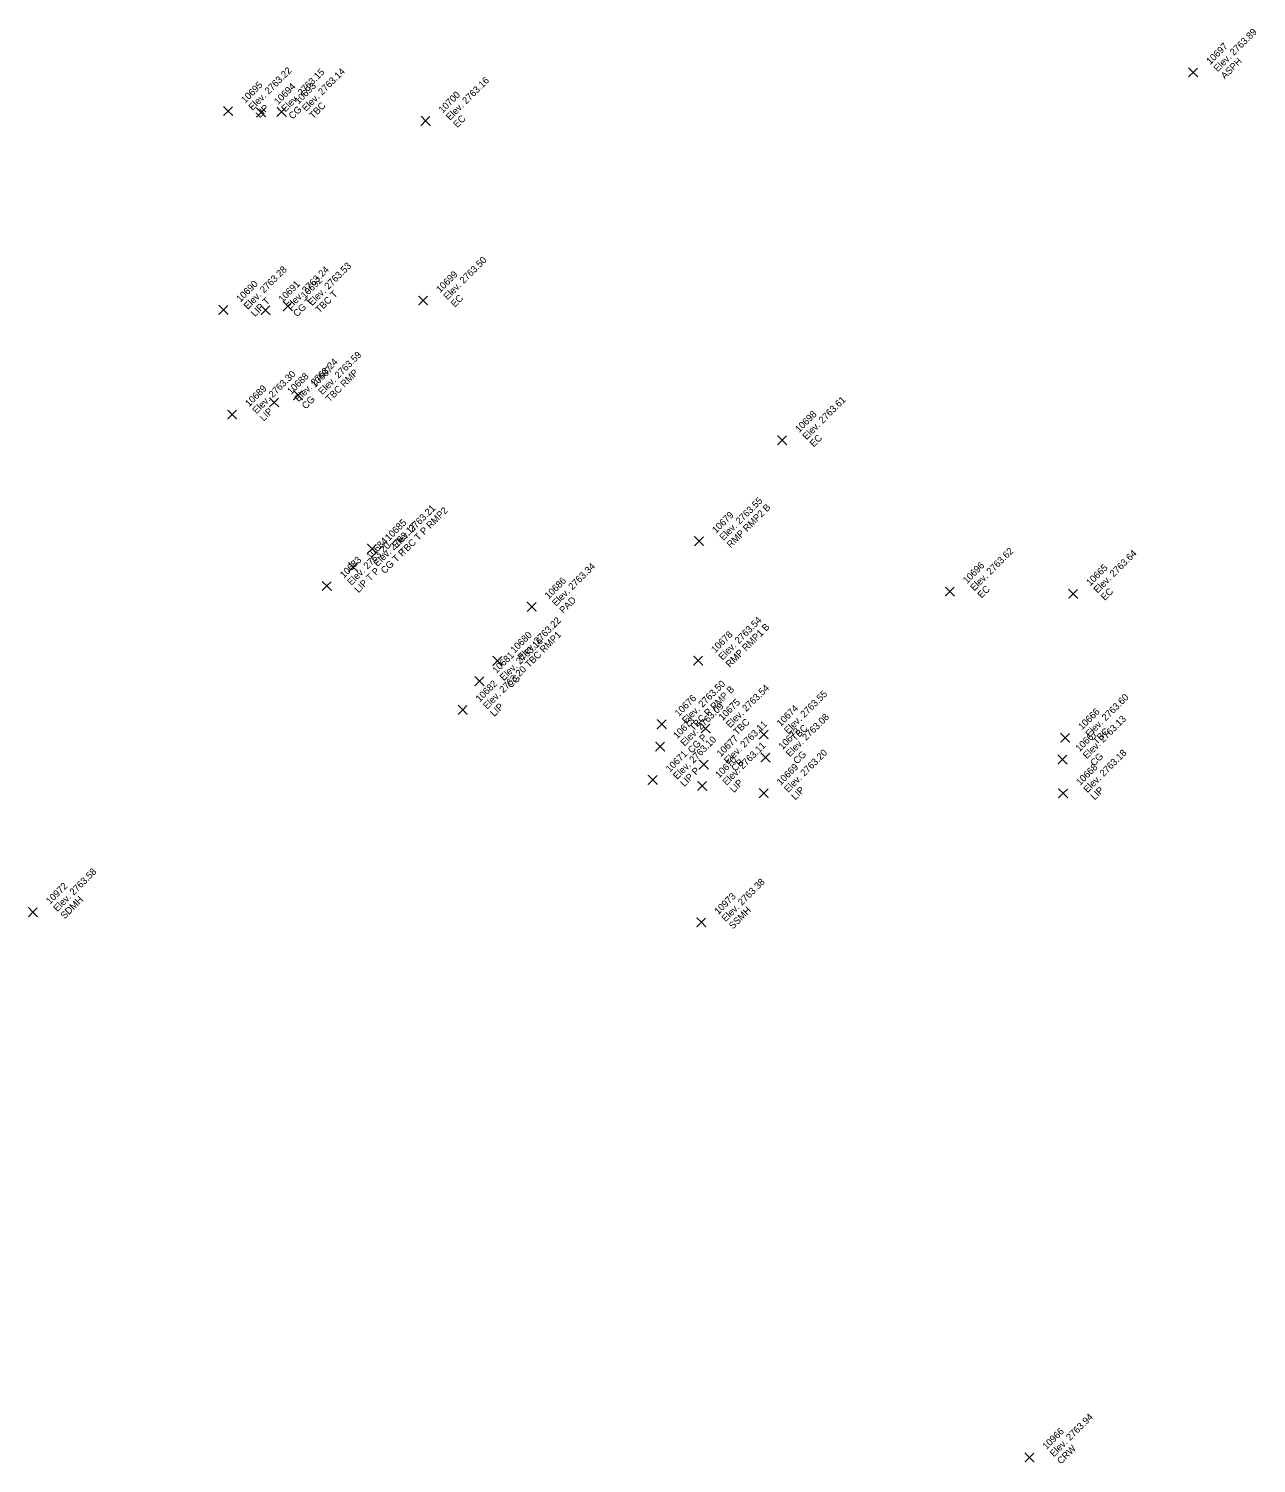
# Model space of a CAD drawing. Extents: x 2493999 to 2503109, y 700767 to 706646.
# Drawn here: x 2502612.8 to 2502655.7, y 701336 to 701386.1 of the extents above; entities that cross this region are included whole.
import ezdxf

# ---------------------------------------------------------------- set-up
doc = ezdxf.new("R2010")
doc.units = 0
doc.layers.add('ALG_CL_BLUE_Horiz', color=7, linetype='Continuous')
doc.layers.add('DES_SURFACE_Existing-Ground', color=7, linetype='Continuous')

msp = doc.modelspace()

# ---------------------------------------------------------------- linework, layer by layer
at = {"layer": 'ALG_CL_BLUE_Horiz'}
for points in [[(2502653.473, 701384.558), (2502653.323, 701384.708), (2502653.473, 701384.558), (2502653.323, 701384.408), (2502653.473, 701384.558), (2502653.623, 701384.408), (2502653.473, 701384.558), (2502653.623, 701384.708)], [(2502619.797, 701383.208), (2502619.647, 701383.358), (2502619.797, 701383.208), (2502619.647, 701383.058), (2502619.797, 701383.208), (2502619.947, 701383.058), (2502619.797, 701383.208), (2502619.947, 701383.358)], [(2502620.945, 701383.156), (2502620.795, 701383.306), (2502620.945, 701383.156), (2502620.795, 701383.006), (2502620.945, 701383.156), (2502621.095, 701383.006), (2502620.945, 701383.156), (2502621.095, 701383.306)], [(2502621.661, 701383.177), (2502621.511, 701383.327), (2502621.661, 701383.177), (2502621.511, 701383.027), (2502621.661, 701383.177), (2502621.811, 701383.027), (2502621.661, 701383.177), (2502621.811, 701383.327)], [(2502626.688, 701382.864), (2502626.538, 701383.014), (2502626.688, 701382.864), (2502626.538, 701382.714), (2502626.688, 701382.864), (2502626.838, 701382.714), (2502626.688, 701382.864), (2502626.838, 701383.014)], [(2502626.601, 701376.599), (2502626.451, 701376.749), (2502626.601, 701376.599), (2502626.451, 701376.449), (2502626.601, 701376.599), (2502626.751, 701376.449), (2502626.601, 701376.599), (2502626.751, 701376.749)], [(2502619.631, 701376.268), (2502619.481, 701376.418), (2502619.631, 701376.268), (2502619.481, 701376.118), (2502619.631, 701376.268), (2502619.781, 701376.118), (2502619.631, 701376.268), (2502619.781, 701376.418)], [(2502621.102, 701376.262), (2502620.952, 701376.412), (2502621.102, 701376.262), (2502620.952, 701376.112), (2502621.102, 701376.262), (2502621.252, 701376.112), (2502621.102, 701376.262), (2502621.252, 701376.412)], [(2502621.878, 701376.397), (2502621.728, 701376.547), (2502621.878, 701376.397), (2502621.728, 701376.247), (2502621.878, 701376.397), (2502622.028, 701376.247), (2502621.878, 701376.397), (2502622.028, 701376.547)], [(2502622.235, 701373.291), (2502622.085, 701373.441), (2502622.235, 701373.291), (2502622.085, 701373.141), (2502622.235, 701373.291), (2502622.385, 701373.141), (2502622.235, 701373.291), (2502622.385, 701373.441)], [(2502619.937, 701372.621), (2502619.787, 701372.771), (2502619.937, 701372.621), (2502619.787, 701372.471), (2502619.937, 701372.621), (2502620.087, 701372.471), (2502619.937, 701372.621), (2502620.087, 701372.771)], [(2502621.405, 701373.045), (2502621.255, 701373.195), (2502621.405, 701373.045), (2502621.255, 701372.895), (2502621.405, 701373.045), (2502621.555, 701372.895), (2502621.405, 701373.045), (2502621.555, 701373.195)], [(2502639.128, 701371.723), (2502638.978, 701371.873), (2502639.128, 701371.723), (2502638.978, 701371.573), (2502639.128, 701371.723), (2502639.278, 701371.573), (2502639.128, 701371.723), (2502639.278, 701371.873)], [(2502636.23, 701368.203), (2502636.08, 701368.353), (2502636.23, 701368.203), (2502636.08, 701368.053), (2502636.23, 701368.203), (2502636.38, 701368.053), (2502636.23, 701368.203), (2502636.38, 701368.353)], [(2502624.817, 701367.94), (2502624.667, 701368.09), (2502624.817, 701367.94), (2502624.667, 701367.79), (2502624.817, 701367.94), (2502624.967, 701367.79), (2502624.817, 701367.94), (2502624.967, 701368.09)], [(2502624.16, 701367.3), (2502624.01, 701367.45), (2502624.16, 701367.3), (2502624.01, 701367.15), (2502624.16, 701367.3), (2502624.31, 701367.15), (2502624.16, 701367.3), (2502624.31, 701367.45)], [(2502623.244, 701366.638), (2502623.094, 701366.788), (2502623.244, 701366.638), (2502623.094, 701366.488), (2502623.244, 701366.638), (2502623.394, 701366.488), (2502623.244, 701366.638), (2502623.394, 701366.788)], [(2502644.981, 701366.446), (2502644.831, 701366.596), (2502644.981, 701366.446), (2502644.831, 701366.296), (2502644.981, 701366.446), (2502645.131, 701366.296), (2502644.981, 701366.446), (2502645.131, 701366.596)], [(2502649.283, 701366.366), (2502649.133, 701366.516), (2502649.283, 701366.366), (2502649.133, 701366.216), (2502649.283, 701366.366), (2502649.433, 701366.216), (2502649.283, 701366.366), (2502649.433, 701366.516)], [(2502630.39, 701365.914), (2502630.24, 701366.064), (2502630.39, 701365.914), (2502630.24, 701365.764), (2502630.39, 701365.914), (2502630.54, 701365.764), (2502630.39, 701365.914), (2502630.54, 701366.064)], [(2502629.193, 701364.023), (2502629.043, 701364.173), (2502629.193, 701364.023), (2502629.043, 701363.873), (2502629.193, 701364.023), (2502629.343, 701363.873), (2502629.193, 701364.023), (2502629.343, 701364.173)], [(2502636.197, 701364.035), (2502636.047, 701364.185), (2502636.197, 701364.035), (2502636.047, 701363.885), (2502636.197, 701364.035), (2502636.347, 701363.885), (2502636.197, 701364.035), (2502636.347, 701364.185)], [(2502628.565, 701363.314), (2502628.415, 701363.464), (2502628.565, 701363.314), (2502628.415, 701363.164), (2502628.565, 701363.314), (2502628.715, 701363.164), (2502628.565, 701363.314), (2502628.715, 701363.464)], [(2502627.981, 701362.321), (2502627.831, 701362.471), (2502627.981, 701362.321), (2502627.831, 701362.171), (2502627.981, 701362.321), (2502628.131, 701362.171), (2502627.981, 701362.321), (2502628.131, 701362.471)], [(2502634.928, 701361.815), (2502634.778, 701361.965), (2502634.928, 701361.815), (2502634.778, 701361.665), (2502634.928, 701361.815), (2502635.078, 701361.665), (2502634.928, 701361.815), (2502635.078, 701361.965)], [(2502636.458, 701361.671), (2502636.308, 701361.821), (2502636.458, 701361.671), (2502636.308, 701361.521), (2502636.458, 701361.671), (2502636.608, 701361.521), (2502636.458, 701361.671), (2502636.608, 701361.821)], [(2502638.485, 701361.461), (2502638.335, 701361.611), (2502638.485, 701361.461), (2502638.335, 701361.311), (2502638.485, 701361.461), (2502638.635, 701361.311), (2502638.485, 701361.461), (2502638.635, 701361.611)], [(2502649.003, 701361.345), (2502648.853, 701361.495), (2502649.003, 701361.345), (2502648.853, 701361.195), (2502649.003, 701361.345), (2502649.153, 701361.195), (2502649.003, 701361.345), (2502649.153, 701361.495)], [(2502634.872, 701361.035), (2502634.722, 701361.185), (2502634.872, 701361.035), (2502634.722, 701360.885), (2502634.872, 701361.035), (2502635.022, 701360.885), (2502634.872, 701361.035), (2502635.022, 701361.185)], [(2502638.55, 701360.659), (2502638.4, 701360.809), (2502638.55, 701360.659), (2502638.4, 701360.509), (2502638.55, 701360.659), (2502638.7, 701360.509), (2502638.55, 701360.659), (2502638.7, 701360.809)], [(2502648.912, 701360.589), (2502648.762, 701360.739), (2502648.912, 701360.589), (2502648.762, 701360.439), (2502648.912, 701360.589), (2502649.062, 701360.439), (2502648.912, 701360.589), (2502649.062, 701360.739)], [(2502636.392, 701360.408), (2502636.242, 701360.558), (2502636.392, 701360.408), (2502636.242, 701360.258), (2502636.392, 701360.408), (2502636.542, 701360.258), (2502636.392, 701360.408), (2502636.542, 701360.558)], [(2502634.613, 701359.871), (2502634.463, 701360.021), (2502634.613, 701359.871), (2502634.463, 701359.721), (2502634.613, 701359.871), (2502634.763, 701359.721), (2502634.613, 701359.871), (2502634.763, 701360.021)], [(2502636.338, 701359.664), (2502636.188, 701359.814), (2502636.338, 701359.664), (2502636.188, 701359.514), (2502636.338, 701359.664), (2502636.488, 701359.514), (2502636.338, 701359.664), (2502636.488, 701359.814)], [(2502638.486, 701359.411), (2502638.336, 701359.561), (2502638.486, 701359.411), (2502638.336, 701359.261), (2502638.486, 701359.411), (2502638.636, 701359.261), (2502638.486, 701359.411), (2502638.636, 701359.561)], [(2502648.93, 701359.405), (2502648.78, 701359.555), (2502648.93, 701359.405), (2502648.78, 701359.255), (2502648.93, 701359.405), (2502649.08, 701359.255), (2502648.93, 701359.405), (2502649.08, 701359.555)], [(2502612.988, 701355.261), (2502612.838, 701355.411), (2502612.988, 701355.261), (2502612.838, 701355.111), (2502612.988, 701355.261), (2502613.138, 701355.111), (2502612.988, 701355.261), (2502613.138, 701355.411)], [(2502636.308, 701354.905), (2502636.158, 701355.055), (2502636.308, 701354.905), (2502636.158, 701354.755), (2502636.308, 701354.905), (2502636.458, 701354.755), (2502636.308, 701354.905), (2502636.458, 701355.055)], [(2502647.758, 701336.237), (2502647.608, 701336.387), (2502647.758, 701336.237), (2502647.608, 701336.087), (2502647.758, 701336.237), (2502647.908, 701336.087), (2502647.758, 701336.237), (2502647.908, 701336.387)]]:
    msp.add_lwpolyline(points, dxfattribs=at)

# ---------------------------------------------------------------- texts
at = {"layer": 'DES_SURFACE_Existing-Ground'}
for s, p in [('Elev. 2763.89', (2502654.322, 701384.558)), ('10697', (2502654.067, 701384.813)), ('Elev. 2763.22', (2502620.646, 701383.208)), ('ASPH', (2502654.576, 701384.303)), ('10695', (2502620.391, 701383.463)), ('Elev. 2763.15', (2502621.794, 701383.156)), ('Elev. 2763.14', (2502622.51, 701383.177)), ('Elev. 2763.16', (2502627.537, 701382.864)), ('10694', (2502621.539, 701383.411)), ('10693', (2502622.255, 701383.432)), ('10700', (2502627.282, 701383.119)), ('LIP', (2502620.9, 701382.953)), ('CG', (2502622.048, 701382.901)), ('TBC', (2502622.764, 701382.922)), ('EC', (2502627.791, 701382.609)), ('Elev. 2763.28', (2502620.48, 701376.268)), ('Elev. 2763.24', (2502621.951, 701376.262)), ('Elev. 2763.53', (2502622.727, 701376.397)), ('Elev. 2763.50', (2502627.45, 701376.599)), ('10690', (2502620.225, 701376.523)), ('10691', (2502621.696, 701376.517)), ('10692', (2502622.472, 701376.652)), ('10699', (2502627.195, 701376.854)), ('LIP T', (2502620.734, 701376.013)), ('TBC T', (2502622.981, 701376.142)), ('EC', (2502627.704, 701376.344)), ('CG T', (2502622.205, 701376.007)), ('Elev. 2763.59', (2502623.084, 701373.291)), ('Elev. 2763.24', (2502622.254, 701373.045)), ('10687', (2502622.829, 701373.546)), ('Elev. 2763.30', (2502620.786, 701372.621)), ('10688', (2502621.999, 701373.3)), ('TBC RMP', (2502623.338, 701373.036)), ('10689', (2502620.531, 701372.876)), ('CG', (2502622.508, 701372.79)), ('Elev. 2763.61', (2502639.977, 701371.723)), ('LIP', (2502621.04, 701372.366)), ('10698', (2502639.722, 701371.978)), ('EC', (2502640.231, 701371.468)), ('Elev. 2763.55', (2502637.079, 701368.203)), ('Elev. 2763.21', (2502625.666, 701367.94)), ('TBC T P RMP2', (2502625.92, 701367.685)), ('10679', (2502636.824, 701368.458)), ('RMP RMP2 B', (2502637.333, 701367.948)), ('Elev. 2763.17', (2502625.009, 701367.3)), ('10685', (2502625.411, 701368.195)), ('10684', (2502624.754, 701367.555)), ('Elev. 2763.20', (2502624.093, 701366.638)), ('CG T P', (2502625.263, 701367.045)), ('Elev. 2763.62', (2502645.83, 701366.446)), ('Elev. 2763.64', (2502650.132, 701366.366)), ('10683', (2502623.838, 701366.893)), ('LIP T P', (2502624.347, 701366.383)), ('Elev. 2763.34', (2502631.239, 701365.914)), ('10696', (2502645.575, 701366.701)), ('10665', (2502649.877, 701366.621)), ('10686', (2502630.984, 701366.169)), ('PAD', (2502631.493, 701365.659)), ('EC', (2502646.084, 701366.191)), ('EC', (2502650.386, 701366.111)), ('Elev. 2763.22', (2502630.042, 701364.023)), ('Elev. 2763.54', (2502637.046, 701364.035)), ('RMP RMP1 B', (2502637.3, 701363.78)), ('Elev. 2763.16', (2502629.414, 701363.314)), ('10680', (2502629.787, 701364.278)), ('TBC RMP1', (2502630.296, 701363.768)), ('10678', (2502636.791, 701364.29)), ('10681', (2502629.159, 701363.569)), ('Elev. 2763.20', (2502628.83, 701362.321)), ('10682', (2502628.575, 701362.576)), ('CG', (2502629.668, 701363.059)), ('Elev. 2763.50', (2502635.777, 701361.815)), ('10676', (2502635.522, 701362.07)), ('TBC P RMP B', (2502636.031, 701361.56)), ('10675', (2502637.052, 701361.926)), ('Elev. 2763.54', (2502637.307, 701361.671)), ('Elev. 2763.55', (2502639.334, 701361.461)), ('Elev. 2763.60', (2502649.852, 701361.345)), ('LIP', (2502629.084, 701362.066)), ('Elev. 2763.09', (2502635.721, 701361.035)), ('10674', (2502639.079, 701361.716)), ('10666', (2502649.597, 701361.6)), ('10673', (2502635.466, 701361.29)), ('Elev. 2763.11', (2502637.241, 701360.408)), ('TBC', (2502637.561, 701361.416)), ('Elev. 2763.08', (2502639.399, 701360.659)), ('TBC', (2502639.588, 701361.206)), ('Elev. 2763.13', (2502649.761, 701360.589)), ('Elev. 2763.10', (2502635.462, 701359.871)), ('CG P', (2502635.975, 701360.78)), ('10677', (2502636.986, 701360.663)), ('10672', (2502639.144, 701360.914)), ('10667', (2502649.506, 701360.844)), ('TBC', (2502650.106, 701361.09)), ('10671', (2502635.207, 701360.126)), ('Elev. 2763.11', (2502637.187, 701359.664)), ('Elev. 2763.20', (2502639.335, 701359.411)), ('CG', (2502639.653, 701360.404)), ('Elev. 2763.18', (2502649.779, 701359.405)), ('CG', (2502650.015, 701360.334)), ('LIP P', (2502635.716, 701359.616)), ('10670', (2502636.932, 701359.919)), ('CB', (2502637.495, 701360.153)), ('10669', (2502639.08, 701359.666)), ('10668', (2502649.524, 701359.66)), ('LIP', (2502637.441, 701359.409)), ('LIP', (2502639.589, 701359.156)), ('LIP', (2502650.033, 701359.15)), ('Elev. 2763.58', (2502613.837, 701355.261)), ('10972', (2502613.582, 701355.516)), ('Elev. 2763.38', (2502637.157, 701354.905)), ('SDMH', (2502614.091, 701355.006)), ('10973', (2502636.902, 701355.16)), ('SSMH', (2502637.411, 701354.65)), ('Elev. 2763.94', (2502648.607, 701336.237)), ('10966', (2502648.352, 701336.492)), ('CRW', (2502648.861, 701335.982))]:
    msp.add_text(s, height=0.24, rotation=45, dxfattribs=at).set_placement(p)

doc.saveas('drawing.dxf')
